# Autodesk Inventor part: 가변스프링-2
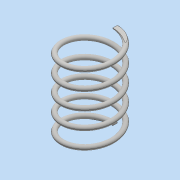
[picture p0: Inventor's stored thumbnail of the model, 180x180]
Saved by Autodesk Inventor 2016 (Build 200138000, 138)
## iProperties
Created: 2015-11
Part Number: 가변스프링-2
Material: 일반
Document SubType Name: Modeling
Designer: Administrator
Density: 1 g/cm^3
Appearance: 기본값
Mass: 1.06136 g
Surface Area: 21.6655 cm^2
Volume: 1.06136 cm^3
Author: Administrator
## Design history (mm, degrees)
sketch "스케치2"
  geometry: L1 (0, 0)-(11, 0); L2 (11, 0)-(11, 29.193); L3 (11, 29.193)-(0, 29.193); L4 (0, 29.193)-(0, 0); C1 r 1 at (11, 0)
  constraints: 8 end point, 2 parallel, 1 centre point, 1 coincident, 1 horizontal, 1 perpendicular
  dimensions: "d0" = 2 diameter of C1; "d1" = 22 diameter of L2 L4; "d2" = 29.19259 distance between parallel lines of L3 L1 (derived)
feature "코일1" sketch "스케치2" pitch "d3" = 10; turns "d5" = 5; dims "d4" = 29.19259 (= d2), "d6" = 0, angle "d7" = 90 deg, angle "d8" = 90 deg, "d9" = 0, "d10" = 0
sketch "스케치3"
  geometry: L1 (0, 12)-(0, 10) reference; 1 further point
  constraints: 1 vertical alignment
extrude "돌출1" cut sketch "스케치3" distance "d11" = 10; taper "d12" = 0 deg
node "작업 평면1"
sketch "스케치4"
  geometry: L1 (0, -1)-(0, 1) reference; 1 further point
  constraints: 1 vertical alignment
extrude "돌출2" cut sketch "스케치4" distance "d13" = 10; taper "d14" = 0 deg
node "솔리드1"
node "절단 모서리 투영1"
node "절단 모서리 투영2"
